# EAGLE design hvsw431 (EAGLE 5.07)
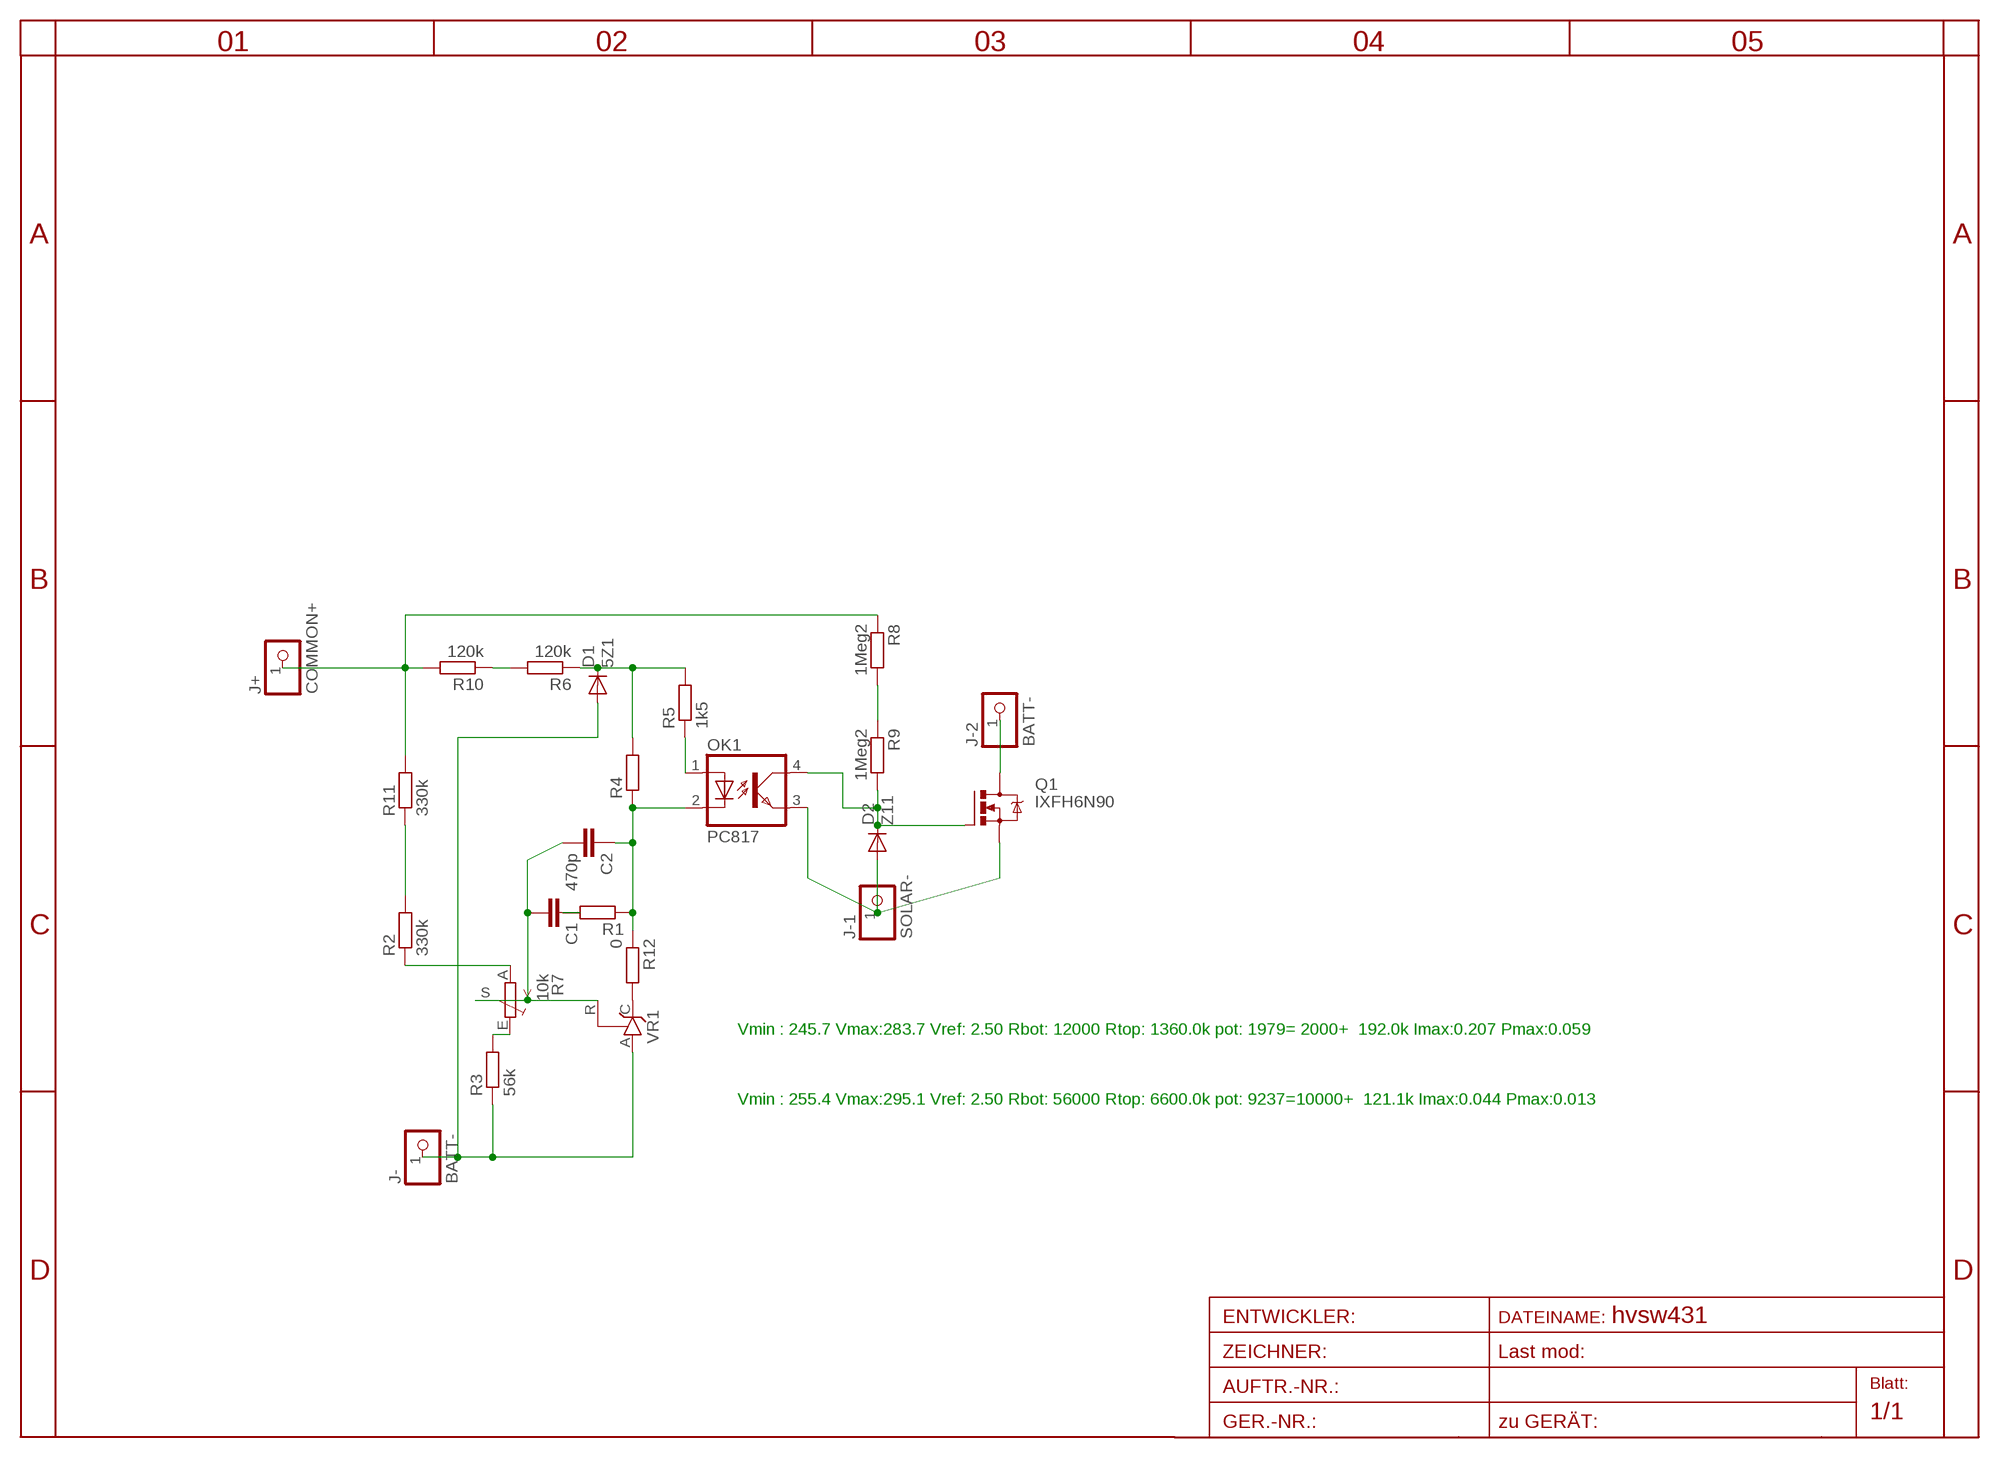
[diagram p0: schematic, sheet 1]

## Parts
C1  C-EUC0805  [C0805]
C2  470p  C-EUC0805  [C0805]
D1  5Z1  DIODE-MINIMELF  [MINIMELF]
D2  Z11  DIODE-MINIMELF  [MINIMELF]
J+  COMMON+  PINHD-1X11X0.4  [1X01]
J-  BATT-  PINHD-1X11X0.4  [1X01]
J-1  SOLAR-  PINHD-1X11X0.4  [1X01]
J-2  BATT-  PINHD-1X11X0.4  [1X01]
OK1  PC817  [DIL04]
Q1  IXFH6N90  [TO-247AD-V]
R1  R-EU_R0805  [R0805]
R2  330k  R-EU_R1206  [R1206]
R3  56k  R-EU_R0805  [R0805]
R4  R-EU_R0805  [R0805]
R5  1k5  R-EU_R0805  [R0805]
R6  120k  R-EU_R1206  [R1206]
R7  10k  TRIM_EU-CA6V  [CA6V]
R8  1Meg2  R-EU_R1206  [R1206]
R9  1Meg2  R-EU_R1206  [R1206]
R10  120k  R-EU_R1206  [R1206]
R11  330k  R-EU_R1206  [R1206]
R12  0  R-EU_R1206  [R1206]
VR1  TL431CLPTO  [TO92-CLP]

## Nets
BATT-: D1.A J-.1 R3.1 VR1.A
D: J-2.1 Q1.D
G: D2.C OK1.4(COL) Q1.G R9.2
N$2: C1.2 C2.2 R7.S VR1.R
N$3: C1.1 R1.2
N$4: R2.1 R7.A
N$5: J+.1 R8.1 R10.2 R11.2
N$7: OK1.1(A) R5.1
N$8: R12.2 VR1.C
N$9: R3.2 R7.E
N$12: R8.2 R9.1
N$15: R2.2 R11.1
N$16: R6.2 R10.1
OK2: C2.1 OK1.2(C) R1.1 R4.1 R12.1
S: D2.A J-1.1 OK1.3(EMIT) Q1.S
V_R: D1.C R4.2 R5.2 R6.1

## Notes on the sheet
- Vmin : 245.7 Vmax:283.7 Vref: 2.50 Rbot: 12000 Rtop: 1360.0k pot: 1979= 2000+  192.0k Imax:0.207 Pmax:0.059
- Vmin : 255.4 Vmax:295.1 Vref: 2.50 Rbot: 56000 Rtop: 6600.0k pot: 9237=10000+  121.1k Imax:0.044 Pmax:0.013

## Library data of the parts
C1 C2 = rcl:C-EU: CAPACITOR, European symbol
D1 D2 = diode:DIODE-: DIODE
J+ J- J-1 J-2 = pinhead:PINHD-1X1: PIN HEADER
OK1 = optocoupler:PC817: SHARP OPTO COUPLER
Q1 = transistor-power:IXF?6N*: HiPerFET (TM) Power MOSFET N-Channel Enhancement Mode HDMOS Family Source: http://www.ixys.com/91529.pdf
R1-R6 R8-R12 = rcl:R-EU_: RESISTOR, European symbol
R7 = pot:TRIM_EU-: POTENTIOMETER
VR1 = v-reg:TL431CLP: VOLTAGE REGULATOR

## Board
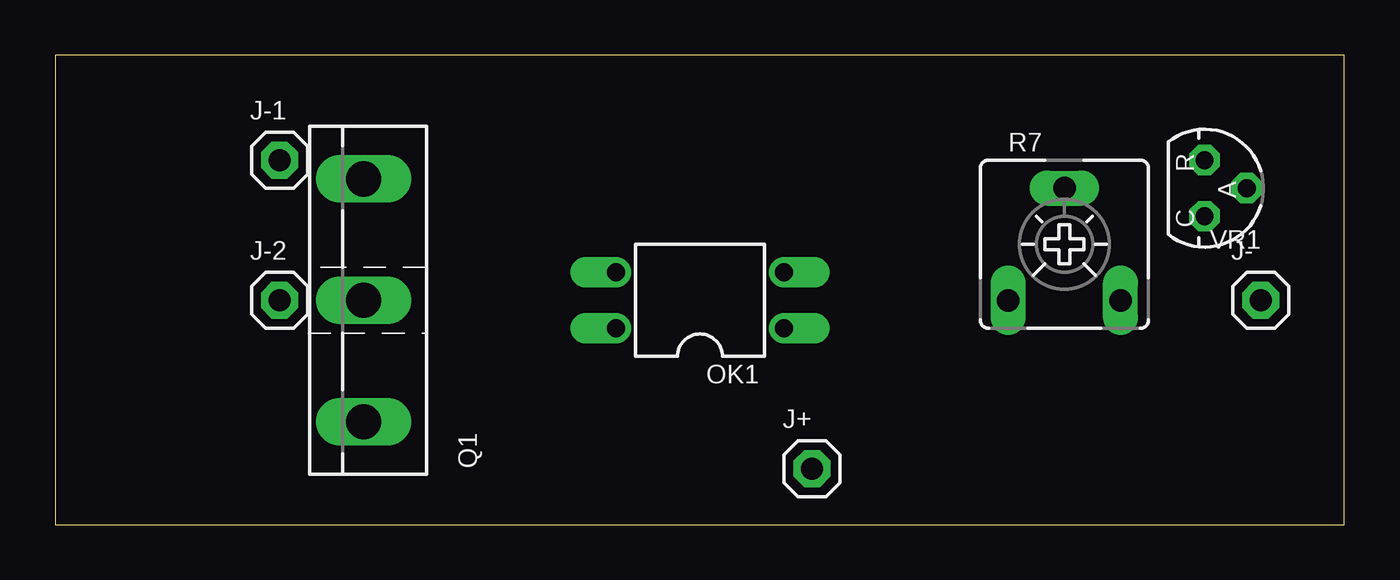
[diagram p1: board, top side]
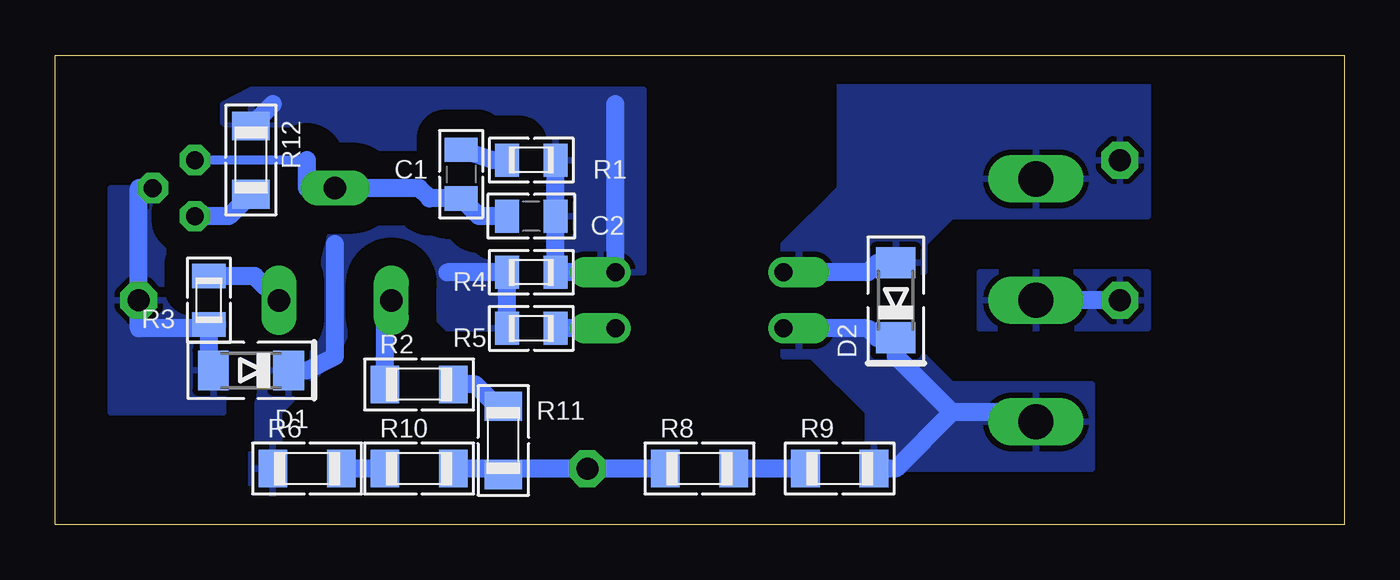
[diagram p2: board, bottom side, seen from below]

Size 58.4 x 21.26 mm. Coordinates in mm from the lower left corner, seen from the top.
Outline: 0,0 58.4,0 58.4,21.26 0,21.26 0,0
Copper layers (1*16): Top 0.035mm / dielectric 1.5mm / Bottom 0.035mm
Design rules "default *": minimum track width 10mil, minimum drill 20mil, track to track 8mil, track to pad 8mil, pad to pad 8mil, via to via 8mil, smd to smd 8mil, copper to edge 40mil, drill to drill 8mil, minimum pad ring 11mil, minimum via ring 8mil, stop-mask expansion 4mil, vias tented up to drill 0mil, thermal gap 10mil

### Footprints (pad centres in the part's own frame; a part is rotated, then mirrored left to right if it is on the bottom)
C0805 = smd 1.1 x 1.5: 1 -1.1,0; 2 1.1,0
MINIMELF = smd 1.4 x 1.8: A 1.7,0; C -1.7,0
1X01 = drill 1 pad 1.676 octagon: 1 0,0
DIL04 = drill 0.813 offset: 1 -1.27,-3.81; 2 1.27,-3.81; 3 1.27,3.81; 4 -1.27,3.81
TO-247AD-V = drill 1.6 long: D 0,-2.54; G -5.5,-2.54; S 5.5,-2.54
R0805 = smd 1.1 x 1.5: 1 -1.1,0; 2 1.1,0
R1206 = smd 1.3 x 1.7: 1 -1.55,0; 2 1.55,0
CA6V = drill 1.016 long: A -2.54,-2.54; E 2.54,-2.54; S 0,2.54
TO92-CLP = drill 0.813 octagon: A 0,1.905; C 1.27,0; R -1.27,0

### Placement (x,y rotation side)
C1  40.01,15.88 270 bottom
C2  36.83,13.97 180 bottom
D1  49.53,6.99 180 bottom
D2  20.32,10.16 90 bottom
J+  34.29,2.54 0 top
J-  54.61,10.16 0 top
J-1  10.16,16.51 0 top
J-2  10.16,10.16 0 top
OK1  29.21,10.16 90 top
Q1  11.43,10.16 90 top
R1  36.83,16.51 180 bottom
R2  41.91,6.35 0 bottom
R3  51.44,10.16 90 bottom
R4  36.83,11.43 180 bottom
R5  36.83,8.89 180 bottom
R6  46.99,2.54 0 bottom
R7  45.72,12.7 0 top
R8  29.21,2.54 0 bottom
R9  22.86,2.54 0 bottom
R10  41.91,2.54 0 bottom
R11  38.1,3.81 270 bottom
R12  49.53,16.51 270 bottom
VR1  52.07,15.24 270 top

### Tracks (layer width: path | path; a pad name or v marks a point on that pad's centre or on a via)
BATT-
  Bottom 0.813: 51.44,8.89 51.44,7.19 D1.A | 51.44,8.89 R3.1 | 51.44,8.89 54.61,8.89 J-.1 54.61,15.24 VR1.A
  pour Bottom (isolate 1.27): 53.34,15.24 55.88,15.24 55.88,5.08 50.8,5.08 50.8,10.16 53.34,10.16
D
  Bottom 0.813: J-2.1 Q1.D
  pour Bottom (isolate 1.27): 8.89,11.43 16.51,11.43 16.51,8.89 8.89,8.89
G
  Bottom 0.813: OK1.4 21.59,8.89 21.16,8.46 D2.C 20.32,7.62 17.78,5.08 | R9.2 20.32,2.54 17.78,5.08 | 17.78,5.08 14.39,5.08 Q1.G
  pour Bottom (isolate 1.27): 12.7,6.35 17.78,6.35 20.32,8.89 25.4,8.89 25.4,7.62 24.13,7.62 21.59,5.08 21.59,2.54 11.43,2.54 11.43,6.35
N$2
  Bottom 0.406: 46.99,16.51 VR1.R
  Bottom 0.813: C2.2 39.2,13.97 C1.2 41.45,14.78 41.91,15.24 R7.S 46.99,15.24 46.99,16.51
N$3
  Bottom 0.813: R1.2 38.56,16.51 C1.1
N$4
  Bottom 0.813: R2.1 43.46,9.88 R7.A
N$5
  Bottom 0.813: R8.1 J+.1 38.1,2.54 | 38.1,2.54 R10.2 | 38.1,2.54 R11.2
N$7
  Bottom 0.813: OK1.1 R5.1
N$8
  Bottom 0.813: VR1.C 50.52,13.97 R12.2
N$9
  Bottom 0.813: R3.2 49.36,11.26 R7.E
N$12
  Bottom 0.813: R9.1 R8.2
N$15
  Bottom 0.813: R11.1 38.38,5.36 39.37,6.35 R2.2
N$16
  Bottom 0.813: R10.1 R6.2
OK2
  Bottom 0.813: R1.1 C2.1 R4.1 OK1.2 33.02,19.05 | R12.1 48.54,19.05
  pour Bottom (isolate 1.27): 31.75,11.43 31.75,19.68 49.53,19.68 50.8,19.05 50.8,16.51 36.83,16.51 36.83,11.43
S
  Bottom 0.813: OK1.3 21.59,11.43 21.16,11.86 D2.A
  pour Bottom (isolate 1.27): 8.89,20.32 22.86,20.32 22.86,15.24 25.4,12.7 25.4,11.43 19.05,11.43 19.05,12.7 17.78,13.97 8.89,13.97
V_R
  Bottom 0.813: R5.2 R4.2 40.64,11.43 | D1.C 46.99,6.99 45.72,7.62 45.72,12.7
  pour Bottom (isolate 1.27, rank 2): 38.1,12.7 39.37,13.97 45.72,13.97 46.99,8.89 49.53,6.35 49.53,1.27 48.26,1.27 48.26,5.08 45.72,7.62 44.45,10.16 41.91,10.16 40.64,8.89 38.1,8.89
